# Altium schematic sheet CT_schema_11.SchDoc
size 742 x 377 mm
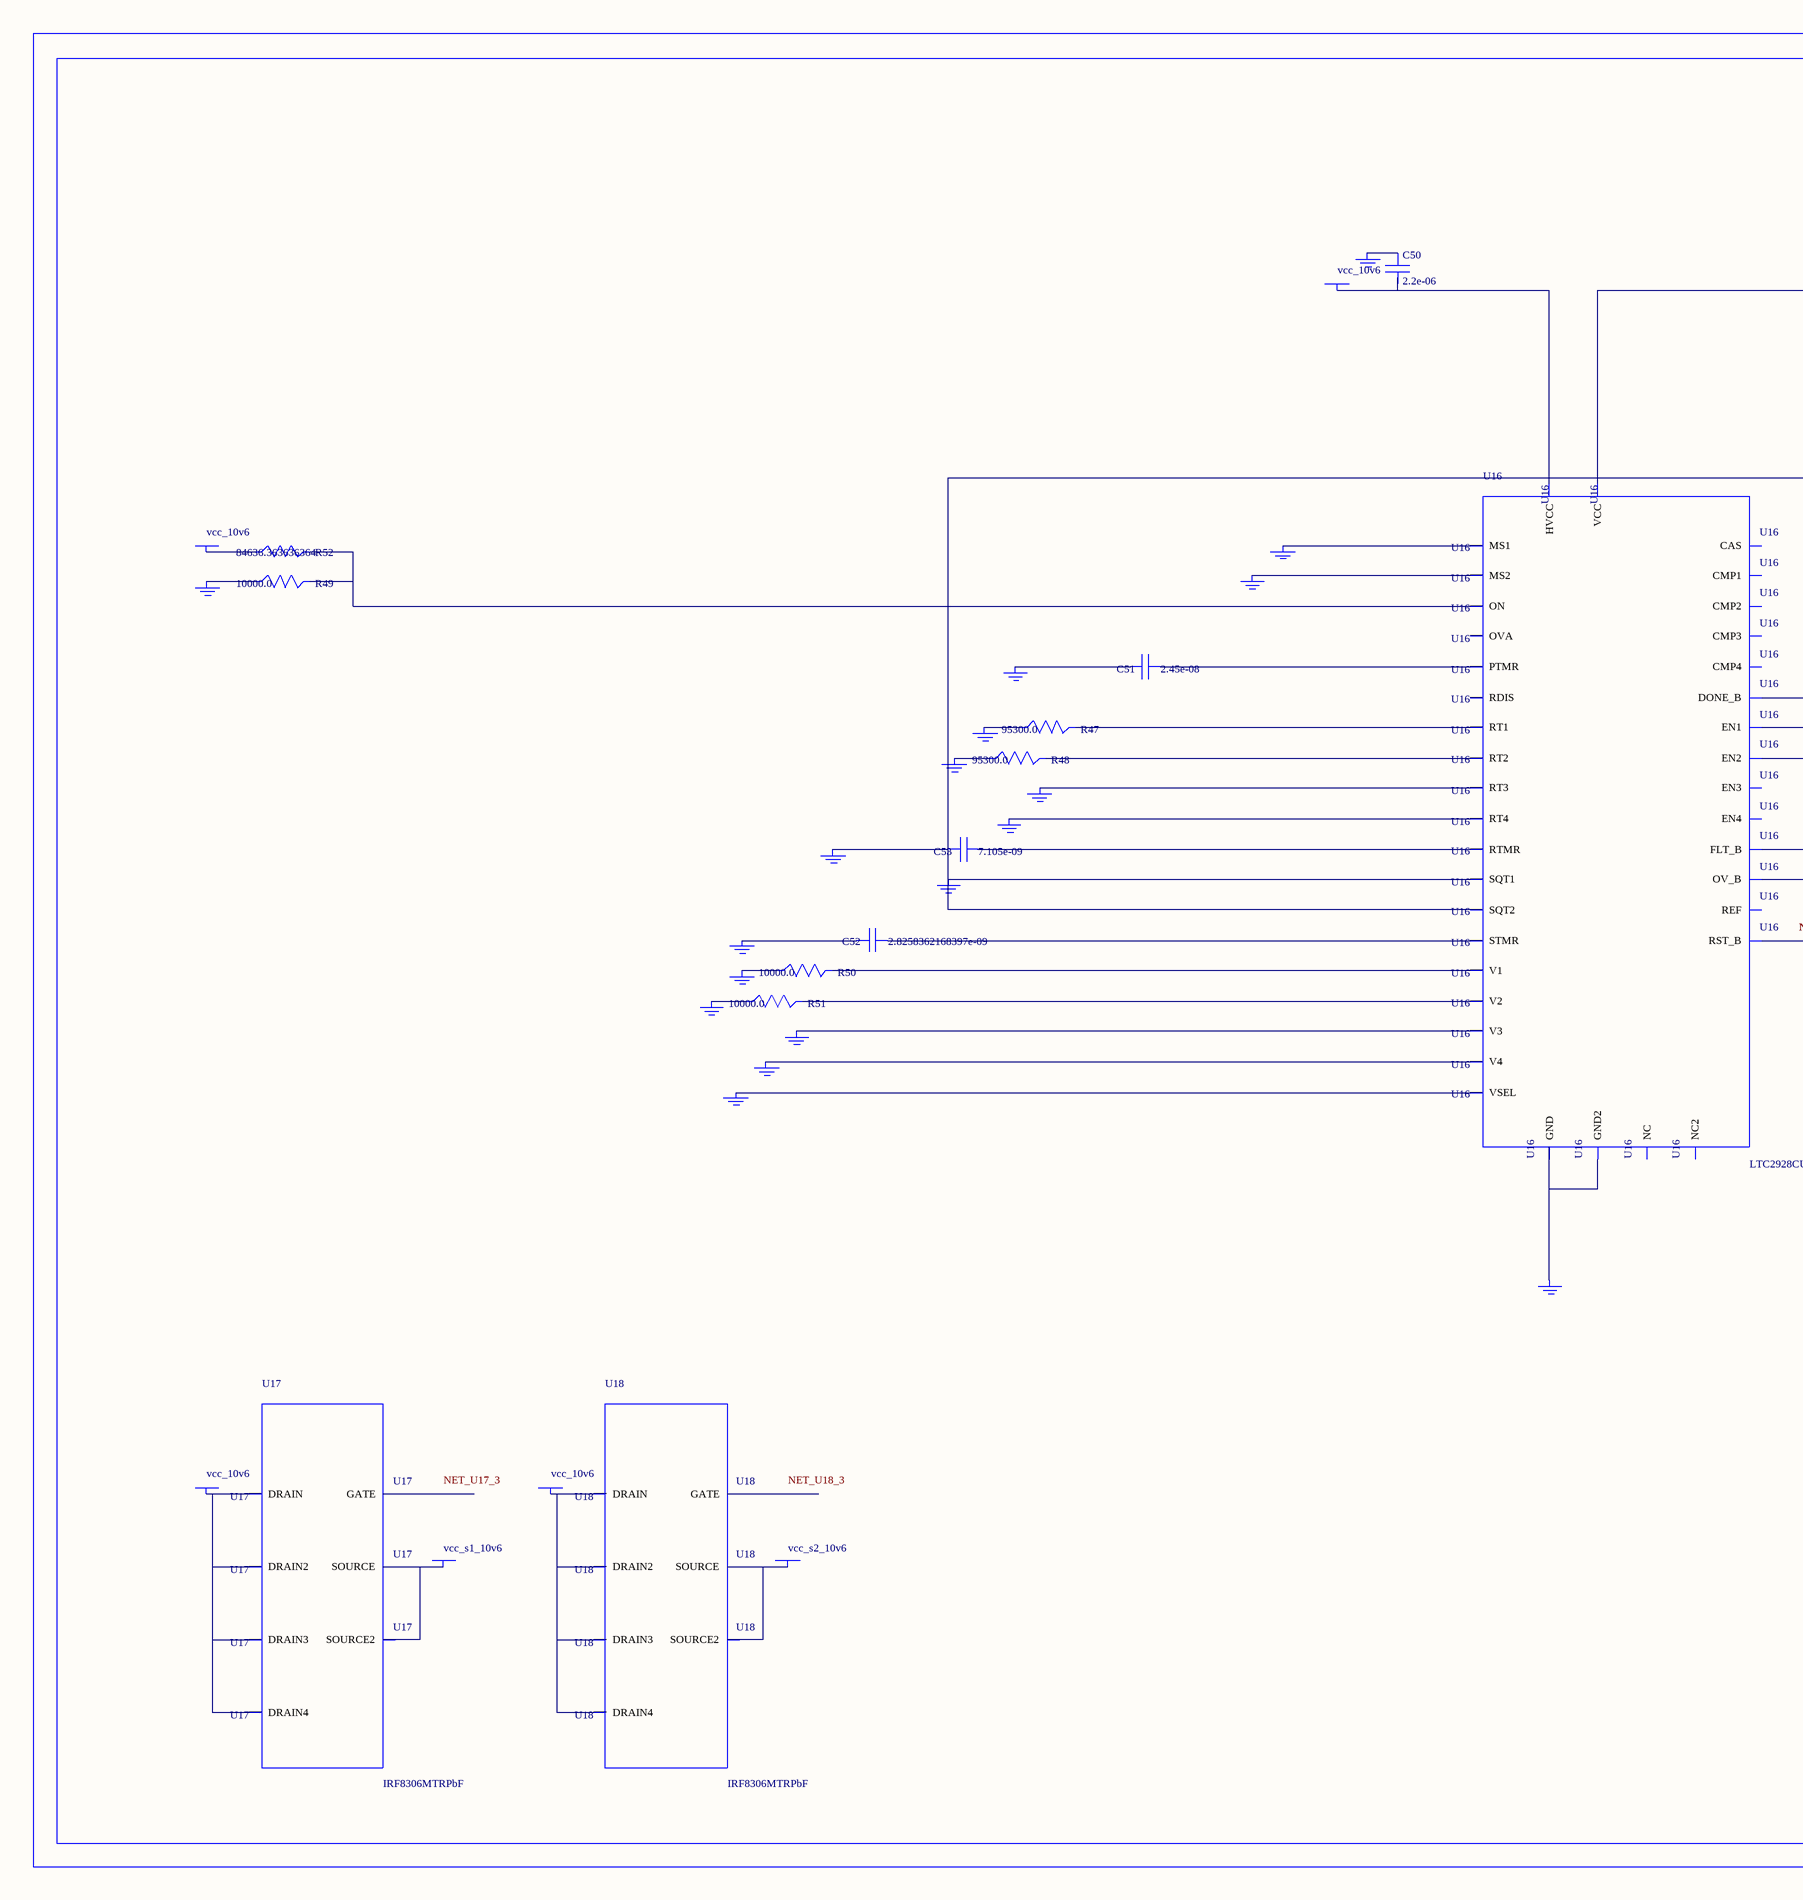
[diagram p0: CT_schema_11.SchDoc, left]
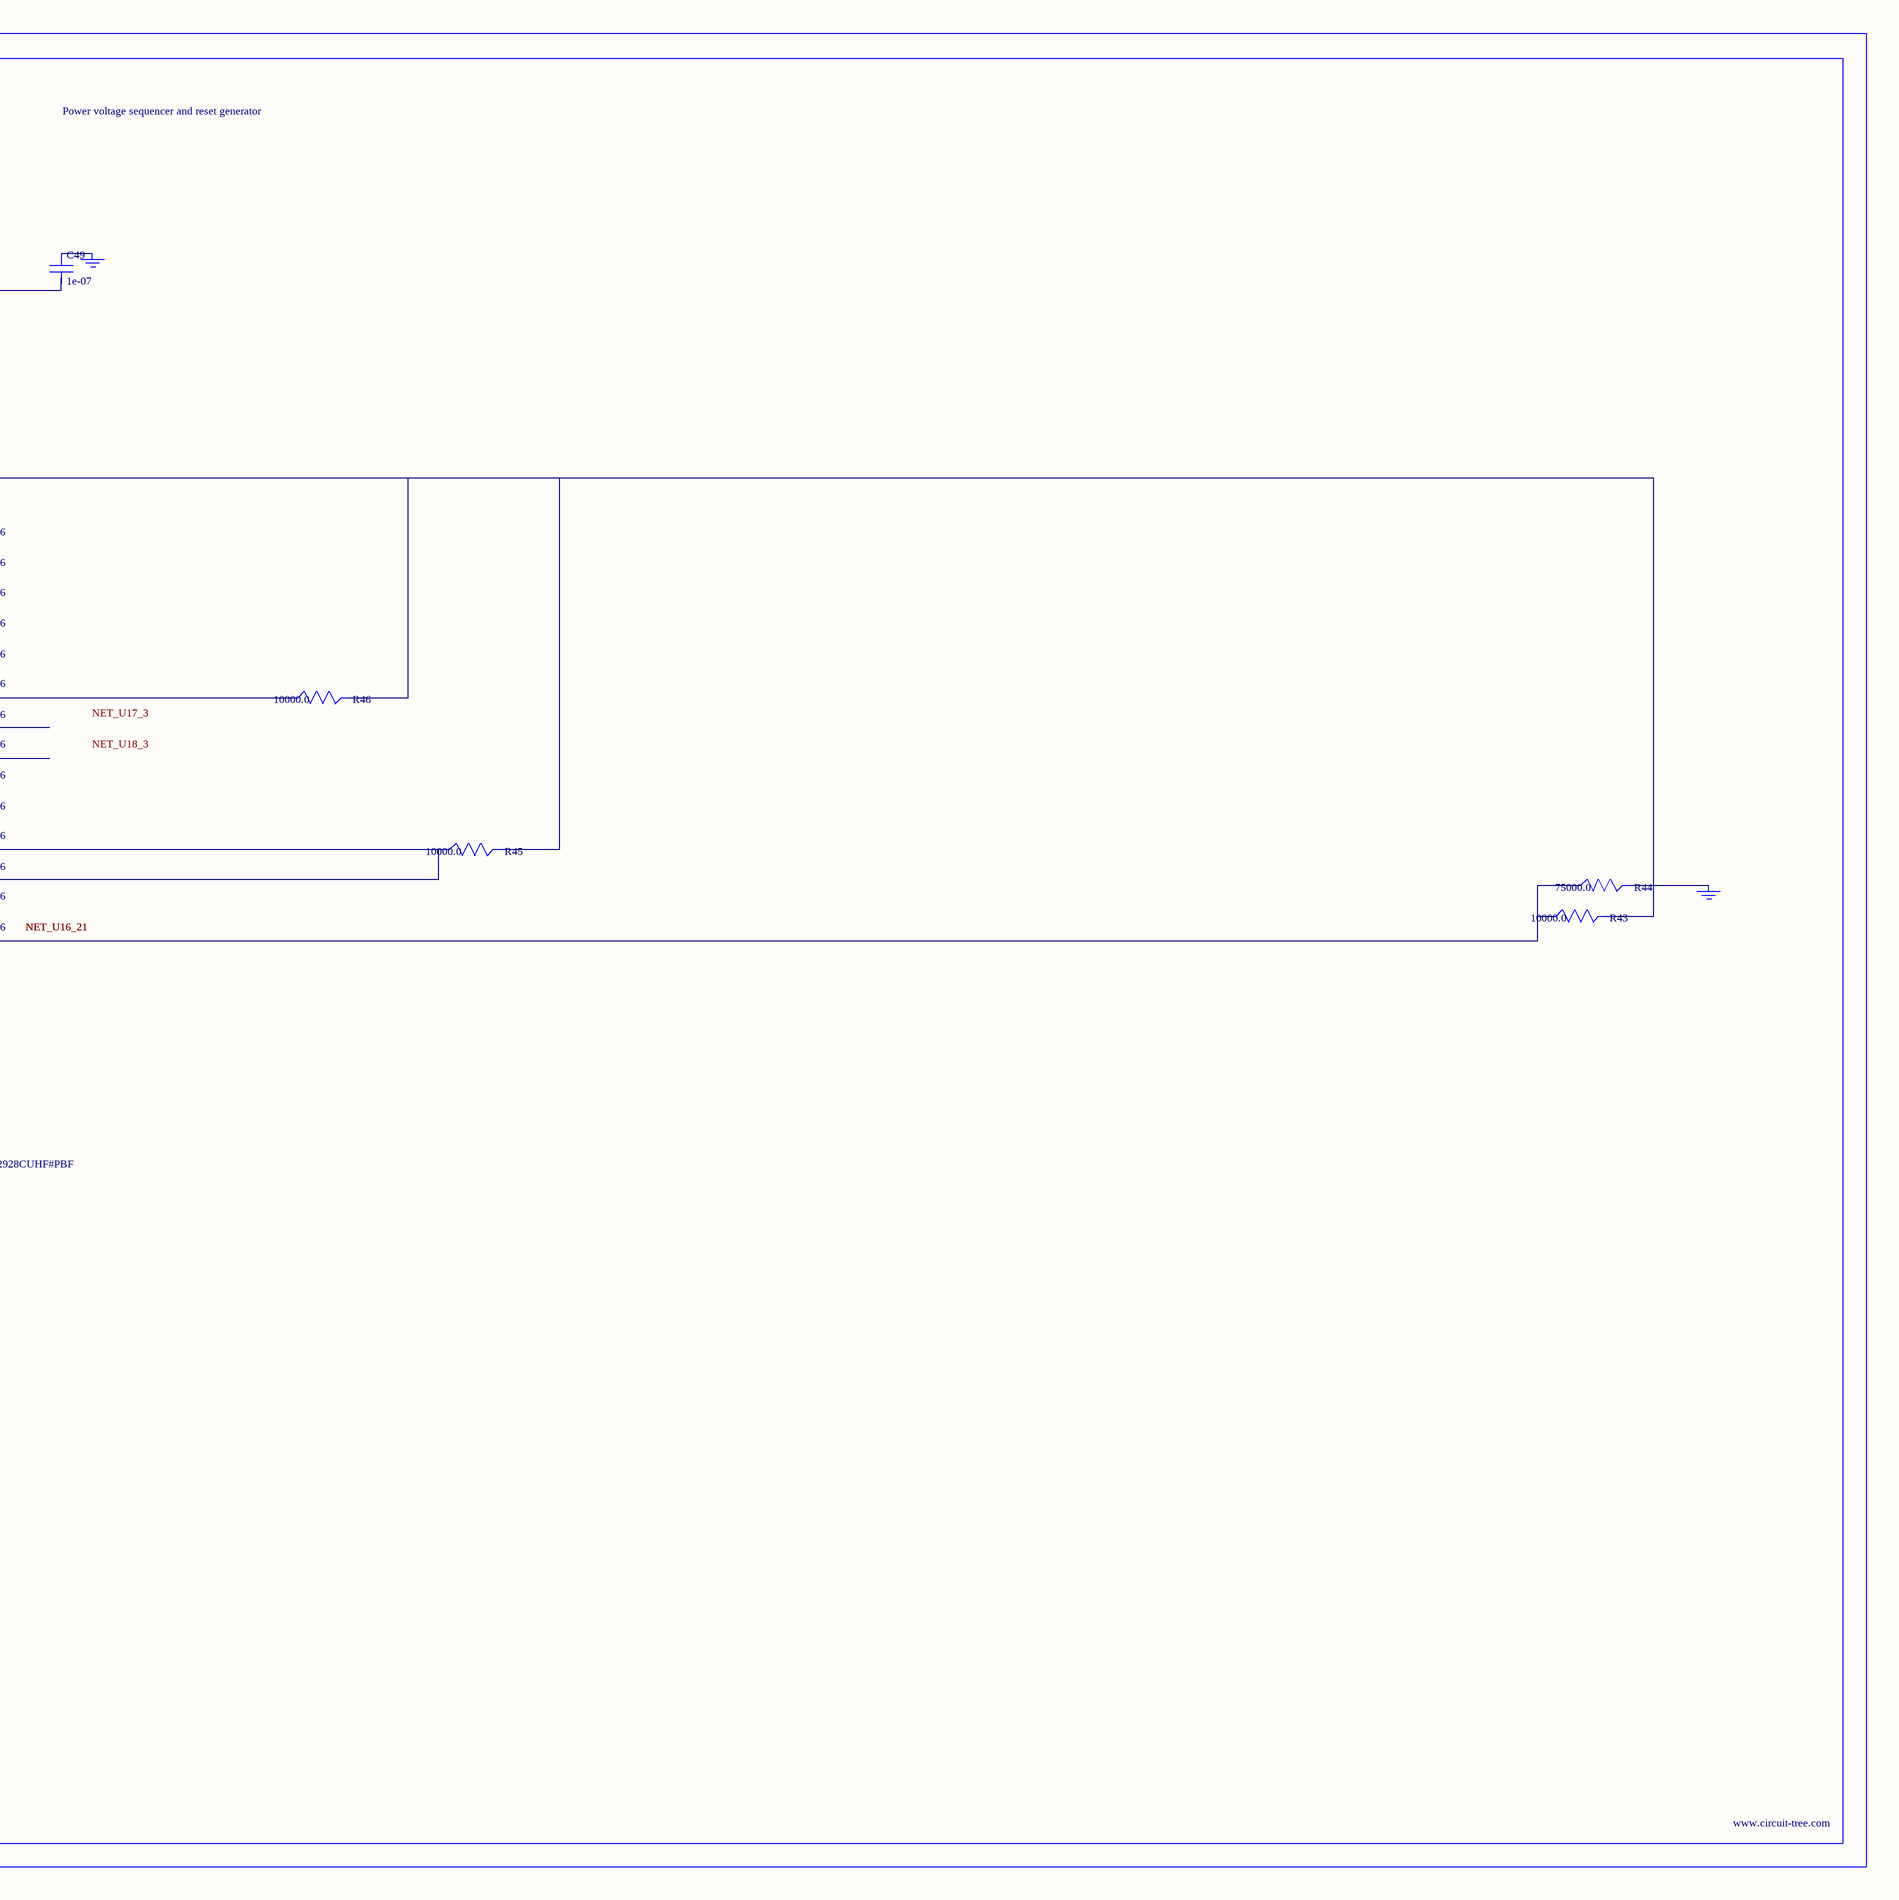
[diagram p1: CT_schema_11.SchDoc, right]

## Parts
BORDER10  (no value)
C49  1e-07  [C0402]
C50  2.2e-06  [C0603]
C51  2.45e-08  [R0603]
C52  2.8258362168397e-09  [R0603]
C53  7.105e-09  [R0603]
GND_INSTANCE_10_0  (no value)
GND_INSTANCE_10_1  (no value)
GND_INSTANCE_10_2  (no value)
GND_INSTANCE_10_3  (no value)
GND_INSTANCE_10_4  (no value)
GND_INSTANCE_10_5  (no value)
GND_INSTANCE_10_6  (no value)
GND_INSTANCE_10_7  (no value)
GND_INSTANCE_10_8  (no value)
GND_INSTANCE_10_9  (no value)
GND_INSTANCE_10_10  (no value)
GND_INSTANCE_10_11  (no value)
GND_INSTANCE_10_12  (no value)
GND_INSTANCE_10_13  (no value)
GND_INSTANCE_10_14  (no value)
GND_INSTANCE_10_15  (no value)
GND_INSTANCE_10_16  (no value)
GND_INSTANCE_10_17  (no value)
GND_INSTANCE_10_18  (no value)
GND_INSTANCE_10_19  (no value)
POWER_INSTANCE_10_0  vcc_10v6
POWER_INSTANCE_10_1  vcc_10v6
POWER_INSTANCE_10_2  vcc_10v6
POWER_INSTANCE_10_3  vcc_s1_10v6
POWER_INSTANCE_10_4  vcc_10v6
POWER_INSTANCE_10_5  vcc_s2_10v6
R43  10000.0  [R0603]
R44  75000.0  [R0603]
R45  10000.0  [R0603]
R46  10000.0  [R0603]
R47  95300.0  [R0603]
R48  95300.0  [R0603]
R49  10000.0  [R0603]
R50  10000.0  [R0603]
R51  10000.0  [R0603]
R52  84636.363636364  [R0603]
U16  LTC2928CUHF#PBF  [QFN-38_UHF]
U17  IRF8306MTRPbF  [IRF8306MTRPBF]
U18  IRF8306MTRPbF  [IRF8306MTRPBF]

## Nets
NetC49_1: C49.1 GND_INSTANCE_10_10.0(GND)
NetC49_2: C49.2 C53.2 GND_INSTANCE_10_5.0(GND) GND_INSTANCE_10_15.0(GND) R43.2 R45.2 R46.2 U16.10(SQT1) U16.11(SQT2) U16.22(VCC)
NetC50_1: C50.1 GND_INSTANCE_10_11.0(GND)
NetC50_2: C50.2 POWER_INSTANCE_10_1.0(PWR) U16.23(HVCC)
NetC51_1: C51.1 U16.27(PTMR)
NetC51_2: C51.2 GND_INSTANCE_10_14.0(GND)
NetC52_1: C52.1 U16.26(STMR)
NetC52_2: C52.2 GND_INSTANCE_10_13.0(GND)
NetC53_1: C53.1 U16.28(RTMR)
NetGND_INSTANCE_10_0_0: GND_INSTANCE_10_0.0(GND) R50.1
NetGND_INSTANCE_10_1_0: GND_INSTANCE_10_1.0(GND) R47.1
NetGND_INSTANCE_10_2_0: GND_INSTANCE_10_2.0(GND) R48.1
NetGND_INSTANCE_10_3_0: GND_INSTANCE_10_3.0(GND) U16.8(RT3)
NetGND_INSTANCE_10_4_0: GND_INSTANCE_10_4.0(GND) U16.9(RT4)
NetGND_INSTANCE_10_6_0: GND_INSTANCE_10_6.0(GND) U16.12(MS1)
NetGND_INSTANCE_10_7_0: GND_INSTANCE_10_7.0(GND) U16.13(MS2)
NetGND_INSTANCE_10_8_0: GND_INSTANCE_10_8.0(GND) R49.1
NetGND_INSTANCE_10_9_0: GND_INSTANCE_10_9.0(GND) R44.2
NetGND_INSTANCE_10_12_0: GND_INSTANCE_10_12.0(GND) U16.25(VSEL)
NetGND_INSTANCE_10_16_0: GND_INSTANCE_10_16.0(GND) U16.30(V4)
NetGND_INSTANCE_10_17_0: GND_INSTANCE_10_17.0(GND) U16.32(V3)
NetGND_INSTANCE_10_18_0: GND_INSTANCE_10_18.0(GND) R51.1
NetGND_INSTANCE_10_19_0: GND_INSTANCE_10_19.0(GND) U16.24(GND) U16.39(GND2)
NetPOWER_INSTANCE_10_0_0: POWER_INSTANCE_10_0.0(PWR) R52.1
NetPOWER_INSTANCE_10_2_0: POWER_INSTANCE_10_2.0(PWR) U17.1(DRAIN) U17.2(DRAIN2) U17.6(DRAIN3) U17.7(DRAIN4)
NetPOWER_INSTANCE_10_3_0: POWER_INSTANCE_10_3.0(PWR) U17.4(SOURCE) U17.5(SOURCE2)
NetPOWER_INSTANCE_10_4_0: POWER_INSTANCE_10_4.0(PWR) U18.1(DRAIN) U18.2(DRAIN2) U18.6(DRAIN3) U18.7(DRAIN4)
NetPOWER_INSTANCE_10_5_0: POWER_INSTANCE_10_5.0(PWR) U18.4(SOURCE) U18.5(SOURCE2)
NetR43_1: R43.1 R44.1 U16.21(RST_B)
NetR45_1: R45.1 U16.19(FLT_B) U16.20(OV_B)
NetR46_1: R46.1 U16.18(DONE_B)
NetR47_2: R47.2 U16.6(RT1)
NetR48_2: R48.2 U16.7(RT2)
NetR49_2: R49.2 R52.2 U16.16(ON)
NetR50_2: R50.2 U16.3(V1)
NetR51_2: R51.2 U16.38(V2)

Not connected (* = marked no-connect by the designer): U16 1(OVA) 2(EN1) 4(NC) 5(REF) 14(RDIS) 15(CAS) 17(NC2) 29(EN4) 31(EN3) 33(CMP3) 34(CMP4) 35(CMP1) 36(CMP2) 37(EN2); U17 3(GATE); U18 3(GATE)

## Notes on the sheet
- Labels drawn without touching a wire or pin: NET_U17_3, NET_U18_3

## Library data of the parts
BORDER10 = BORDER_PAGE10
C49 = C0402C104K3RACTU
C50 = GRM188R61H225KE1115D
C51 = C51
C52 = C52
C53 = C53
GND_INSTANCE_10_0-GND_INSTANCE_10_19 = GND
POWER_INSTANCE_10_0-POWER_INSTANCE_10_5 = PWR
R43 R45 R46 R49-R51 = RC0603JR-0710KL
R44 = RC0603JR-0775KL
R47 R48 = RC0603FR-0795K3L
R52 = R52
